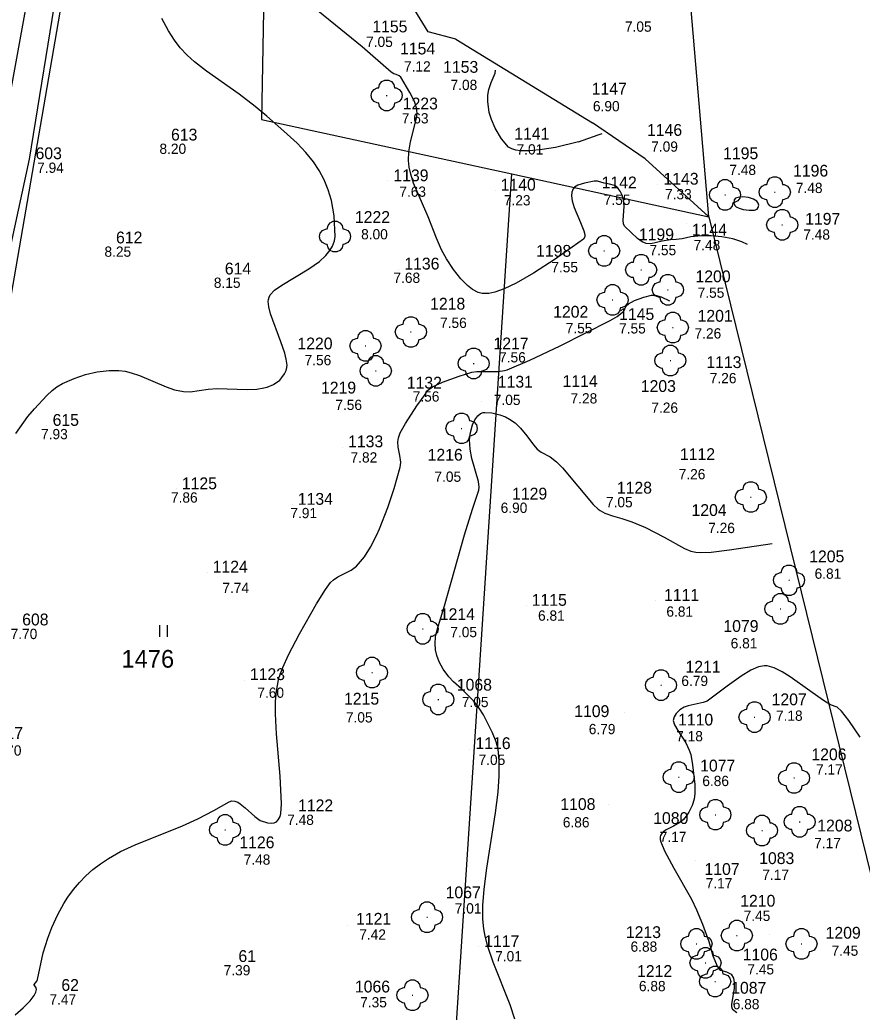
# Model space of a CAD drawing. Extents: x -792549 to -792339, y -1111914 to -1111617.
# Drawn here: x -792466.04 to -792438.93, y -1111801.86 to -1111769.94 of the extents above; entities that cross this region are included whole.
import ezdxf

# ---------------------------------------------------------------- set-up
doc = ezdxf.new("R2010")
doc.units = 0
for name, color, linetype in [('Vrstva 1', 7, 'Continuous'), ('Vrstva 10', 7, 'Continuous'), ('Vrstva 32', 7, 'Continuous'), ('Vrstva 33', 7, 'Continuous'), ('Vrstva 41', 7, 'Continuous'), ('Vrstva 42', 7, 'Continuous'), ('Vrstva 44', 7, 'Continuous'), ('Vrstva 46', 7, 'Continuous'), ('Vrstva 48', 7, 'Continuous'), ('Vrstva 49', 7, 'Continuous'), ('Vrstva 50', 7, 'Continuous')]:
    doc.layers.add(name, color=color, linetype=linetype)

# ---------------------------------------------------------------- blocks, each defined once
blk = doc.blocks.new('3$0600')
at = {"layer": 'Vrstva 1'}
for p, q in [((-5, 15), (-5, 0)), ((5, 0), (5, 15))]:
    blk.add_line(p, q, dxfattribs=at)
blk = doc.blocks.new('SC6231')
at = {"layer": 'Vrstva 1'}
blk.add_line((0, 0), (0, 0), dxfattribs=at)
blk = doc.blocks.new('3$1300')
at = {"layer": 'Vrstva 1'}
for points in [[(20, 0), (19, -4.3), (16.2, -7.8), (12.2, -9.7), (10, -10), (9, -14.3), (6.2, -17.8), (2.2, -19.7), (-2.3, -19.7), (-6.3, -17.8), (-9.1, -14.3), (-10.1, -10), (-12.3, -9.7), (-16.3, -7.8), (-19.1, -4.3), (-20.1, 0), (-19.1, 4.3), (-16.3, 7.8), (-12.3, 9.7), (-10.1, 10), (-9.1, 14.3), (-6.3, 17.8), (-2.3, 19.7), (2.2, 19.7), (6.2, 17.8), (9, 14.3), (10, 10), (12.2, 9.7), (16.2, 7.8), (19, 4.3), (20, 0)], [(-0.5, 0), (0, 0), (0.5, 0)]]:
    blk.add_lwpolyline(points, dxfattribs=at)

msp = doc.modelspace()

# ---------------------------------------------------------------- linework, layer by layer
at = {"layer": 'Vrstva 10'}
for p, q in [((-792452.01, -1111770.56), (-792447.61, -1111773.25)), ((-792445.91, -1111774.41), (-792447.61, -1111773.25)), ((-792445.91, -1111774.41), (-792443.86, -1111776.27))]:
    msp.add_line(p, q, dxfattribs=at)
msp.add_lwpolyline([(-792452.01, -1111770.56), (-792452.9, -1111770.32), (-792453.32, -1111769.63), (-792453.87, -1111768.96), (-792455.06, -1111766.69), (-792455.4, -1111763.77), (-792455.2, -1111759.42), (-792454.58, -1111756.26)], dxfattribs=at)
at = {"layer": 'Vrstva 32'}
for points in [[(-792466.167, -1111783.244), (-792465.781, -1111782.703), (-792465.562, -1111782.449), (-792465.168, -1111782.023), (-792464.995, -1111781.864), (-792464.848, -1111781.748), (-792464.659, -1111781.638), (-792464.293, -1111781.476), (-792463.922, -1111781.352), (-792463.543, -1111781.263), (-792463.161, -1111781.214), (-792462.851, -1111781.219), (-792462.647, -1111781.245), (-792462.451, -1111781.289), (-792462.187, -1111781.376), (-792461.328, -1111781.747), (-792461.056, -1111781.842), (-792460.774, -1111781.9), (-792460.559, -1111781.91), (-792459.98, -1111781.817), (-792459.69, -1111781.8), (-792458.721, -1111781.83), (-792458.408, -1111781.817), (-792458.185, -1111781.782), (-792458.078, -1111781.756), (-792457.872, -1111781.672), (-792457.669, -1111781.527), (-792457.6, -1111781.447), (-792457.516, -1111781.323), (-792457.464, -1111781.218), (-792457.439, -1111781.125), (-792457.434, -1111781.046), (-792457.463, -1111780.854), (-792457.512, -1111780.662), (-792457.633, -1111780.297), (-792457.965, -1111779.394), (-792458.024, -1111779.173), (-792458.041, -1111779.001), (-792458.035, -1111778.931), (-792458.015, -1111778.86), (-792457.979, -1111778.79), (-792457.84, -1111778.639), (-792457.604, -1111778.469), (-792456.737, -1111777.953), (-792456.397, -1111777.707), (-792456.19, -1111777.515), (-792456.06, -1111777.356), (-792455.975, -1111777.219), (-792455.91, -1111777.048), (-792455.89, -1111776.91), (-792455.924, -1111776.238), (-792456.009, -1111775.751), (-792456.111, -1111775.406), (-792456.244, -1111775.083), (-792456.401, -1111774.786), (-792456.583, -1111774.51), (-792456.832, -1111774.202), (-792457.113, -1111773.908), (-792457.536, -1111773.521), (-792458.086, -1111773.039), (-792458.459, -1111772.726), (-792458.98, -1111772.333), (-792460.029, -1111771.591), (-792460.42, -1111771.286), (-792460.656, -1111771.074), (-792460.875, -1111770.843), (-792461.064, -1111770.592), (-792461.248, -1111770.296), (-792461.463, -1111769.894)], [(-792448.055, -1111773.866), (-792448.799, -1111774.042), (-792449.222, -1111774.114), (-792449.619, -1111774.151), (-792449.908, -1111774.147), (-792450.071, -1111774.127), (-792450.201, -1111774.089), (-792450.306, -1111774.029), (-792450.54, -1111773.763), (-792450.737, -1111773.424), (-792450.857, -1111773.14), (-792450.928, -1111772.923), (-792450.98, -1111772.562), (-792450.973, -1111772.356), (-792450.943, -1111772.18), (-792450.869, -1111771.954), (-792450.743, -1111771.648), (-792450.726, -1111771.554)], [(-792448.055, -1111773.866), (-792447.425, -1111773.636), (-792447.299, -1111773.59)], [(-792451.276, -1111784.792), (-792451.491, -1111784.047), (-792451.549, -1111783.745), (-792451.565, -1111783.45), (-792451.537, -1111783.214), (-792451.467, -1111782.966), (-792451.392, -1111782.805), (-792451.302, -1111782.682), (-792451.21, -1111782.604), (-792451.128, -1111782.571), (-792451.068, -1111782.566), (-792450.846, -1111782.584), (-792450.594, -1111782.641), (-792450.409, -1111782.712), (-792450.275, -1111782.78), (-792450.097, -1111782.906), (-792449.92, -1111783.076), (-792449.724, -1111783.321), (-792449.509, -1111783.613), (-792449.386, -1111783.748), (-792449.257, -1111783.848), (-792448.965, -1111784.002), (-792448.77, -1111784.155), (-792448.572, -1111784.354), (-792447.587, -1111785.527), (-792447.428, -1111785.679), (-792447.358, -1111785.727), (-792447.214, -1111785.805), (-792446.967, -1111785.897), (-792446.664, -1111785.98), (-792446.345, -1111786.085), (-792445.905, -1111786.273), (-792445.297, -1111786.578), (-792444.641, -1111786.949), (-792444.445, -1111787.031), (-792444.28, -1111787.069), (-792444.125, -1111787.08), (-792443.793, -1111787.064), (-792443.197, -1111786.988), (-792441.824, -1111786.785)], [(-792450.106, -1111802.093), (-792450.258, -1111801.629), (-792450.801, -1111800.255), (-792450.979, -1111799.751), (-792451.064, -1111799.424), (-792451.107, -1111799.184), (-792451.135, -1111798.867), (-792451.136, -1111798.434), (-792451.098, -1111797.907), (-792451.01, -1111797.231), (-792450.724, -1111795.453), (-792450.642, -1111794.787), (-792450.606, -1111794.256), (-792450.61, -1111793.762), (-792450.647, -1111793.398), (-792450.707, -1111793.162), (-792450.82, -1111792.882), (-792451.117, -1111792.294), (-792451.25, -1111792.078), (-792451.441, -1111791.845), (-792451.814, -1111791.47), (-792452.077, -1111791.235), (-792452.23, -1111791.074), (-792452.411, -1111790.825), (-792452.539, -1111790.593), (-792452.619, -1111790.387), (-792452.659, -1111790.206), (-792452.674, -1111790.008), (-792452.658, -1111789.789), (-792452.611, -1111789.567), (-792452.365, -1111788.793), (-792451.721, -1111786.504), (-792451.467, -1111785.685), (-792451.263, -1111785.065), (-792451.252, -1111784.968), (-792451.276, -1111784.792)], [(-792438.995, -1111793.017), (-792439.359, -1111792.485), (-792439.599, -1111792.182), (-792439.735, -1111792.054), (-792439.944, -1111791.972), (-792440.174, -1111791.841), (-792440.618, -1111791.531), (-792441.241, -1111791.08), (-792441.501, -1111790.917), (-792441.756, -1111790.79), (-792441.987, -1111790.72), (-792442.073, -1111790.718), (-792442.267, -1111790.755), (-792442.509, -1111790.866), (-792442.825, -1111791.056), (-792443.277, -1111791.379), (-792443.918, -1111791.856), (-792444.042, -1111791.901), (-792444.531, -1111792.005), (-792444.661, -1111792.055), (-792444.793, -1111792.137), (-792444.915, -1111792.254), (-792444.984, -1111792.363), (-792445.007, -1111792.475), (-792444.969, -1111792.616), (-792444.864, -1111792.8), (-792444.607, -1111793.195), (-792444.491, -1111793.433), (-792444.446, -1111793.574), (-792444.386, -1111793.91), (-792444.319, -1111794.542), (-792444.311, -1111794.833), (-792444.337, -1111795.009), (-792444.403, -1111795.211), (-792444.509, -1111795.431), (-792444.589, -1111795.557), (-792444.682, -1111795.666), (-792444.797, -1111795.763), (-792444.998, -1111795.879), (-792445.255, -1111796.007), (-792445.363, -1111796.09), (-792445.421, -1111796.179), (-792445.429, -1111796.221), (-792445.425, -1111796.311), (-792445.408, -1111796.389), (-792445.291, -1111796.67), (-792444.989, -1111797.226), (-792444.423, -1111798.233), (-792444.255, -1111798.567), (-792444.07, -1111799.03), (-792443.864, -1111799.594), (-792443.73, -1111800.055), (-792443.583, -1111800.403), (-792443.515, -1111800.496), (-792443.485, -1111800.516), (-792443.294, -1111800.566), (-792443.142, -1111800.641), (-792443.074, -1111800.769), (-792443.048, -1111800.906), (-792443.053, -1111801.094), (-792443.133, -1111801.615), (-792443.133, -1111801.677), (-792443.115, -1111801.755), (-792443.102, -1111801.772), (-792442.966, -1111801.872)]]:
    msp.add_lwpolyline(points, dxfattribs=at)
at = {"layer": 'Vrstva 33'}
for points in [[(-792442.62, -1111777.166), (-792442.796, -1111777.078), (-792443.086, -1111776.985), (-792443.447, -1111776.914), (-792443.788, -1111776.882), (-792444.101, -1111776.884), (-792444.447, -1111776.92), (-792444.725, -1111776.98), (-792444.912, -1111777.005), (-792445.092, -1111777.015), (-792445.36, -1111777.06), (-792445.734, -1111777.14), (-792445.884, -1111777.135), (-792446.007, -1111777.083), (-792446.162, -1111776.973), (-792446.567, -1111776.581), (-792446.607, -1111776.513), (-792446.617, -1111776.391), (-792446.592, -1111775.936), (-792446.607, -1111775.728), (-792446.649, -1111775.575), (-792446.713, -1111775.449), (-792446.815, -1111775.325), (-792446.896, -1111775.271), (-792447.061, -1111775.222), (-792447.231, -1111775.189), (-792447.45, -1111775.128), (-792447.553, -1111775.13), (-792447.868, -1111775.192), (-792448.08, -1111775.26), (-792448.185, -1111775.326), (-792448.229, -1111775.378), (-792448.268, -1111775.483), (-792448.282, -1111775.6), (-792448.264, -1111775.76), (-792448.201, -1111775.974), (-792447.988, -1111776.462), (-792447.883, -1111776.722), (-792447.856, -1111776.847), (-792447.859, -1111776.922), (-792447.897, -1111776.99), (-792448.804, -1111777.633), (-792449.51, -1111778.086), (-792450.068, -1111778.405), (-792450.452, -1111778.592), (-792450.753, -1111778.702), (-792450.944, -1111778.743), (-792451.162, -1111778.746), (-792451.288, -1111778.711), (-792451.465, -1111778.614), (-792451.629, -1111778.483), (-792451.84, -1111778.271), (-792452.082, -1111777.97), (-792452.309, -1111777.626), (-792452.467, -1111777.335), (-792452.631, -1111776.957), (-792452.898, -1111776.274), (-792453.372, -1111775.194), (-792453.458, -1111774.905), (-792453.512, -1111774.68), (-792453.532, -1111774.46), (-792453.521, -1111774.185), (-792453.468, -1111773.862), (-792453.27, -1111773.105), (-792453.251, -1111772.944), (-792453.266, -1111772.769), (-792453.335, -1111772.563), (-792453.483, -1111772.28), (-792453.777, -1111771.782), (-792453.828, -1111771.734), (-792453.923, -1111771.696), (-792454.004, -1111771.676), (-792454.087, -1111771.618), (-792455.021, -1111770.805), (-792457.138, -1111769.074)], [(-792443.048, -1111775.723), (-792443.061, -1111775.833), (-792443.028, -1111775.906), (-792442.98, -1111775.951), (-792442.886, -1111775.998), (-792442.756, -1111776.034), (-792442.567, -1111776.058), (-792442.396, -1111776.056), (-792442.313, -1111776.026), (-792442.271, -1111775.979), (-792442.257, -1111775.903), (-792442.273, -1111775.839), (-792442.323, -1111775.768), (-792442.424, -1111775.702), (-792442.584, -1111775.648), (-792442.771, -1111775.63), (-792442.922, -1111775.649), (-792443, -1111775.677), (-792443.048, -1111775.723)], [(-792458.782, -1111795.293), (-792458.478, -1111795.572), (-792458.304, -1111795.693), (-792458.068, -1111795.774), (-792457.951, -1111795.785), (-792457.856, -1111795.77), (-792457.779, -1111795.736), (-792457.718, -1111795.68), (-792457.66, -1111795.566), (-792457.636, -1111795.47), (-792457.62, -1111795.166), (-792457.659, -1111794.275), (-792457.78, -1111792.909), (-792457.81, -1111792.267), (-792457.805, -1111791.867), (-792457.78, -1111791.539), (-792457.715, -1111791.174), (-792457.692, -1111791.089), (-792457.578, -1111790.779), (-792457.393, -1111790.371), (-792457.037, -1111789.688), (-792456.493, -1111788.731), (-792456.201, -1111788.265), (-792456.036, -1111788.04), (-792455.942, -1111787.949), (-792455.798, -1111787.856), (-792455.369, -1111787.645), (-792455.198, -1111787.515), (-792454.949, -1111787.212), (-792454.755, -1111786.908), (-792454.562, -1111786.527), (-792454.467, -1111786.309), (-792454.198, -1111785.629), (-792453.986, -1111785.013), (-792453.797, -1111784.326), (-792453.785, -1111784.266), (-792453.78, -1111784.166), (-792453.811, -1111783.955), (-792453.862, -1111783.689), (-792453.87, -1111783.516), (-792453.85, -1111783.385), (-792453.792, -1111783.226), (-792453.628, -1111782.927), (-792453.263, -1111782.36), (-792452.995, -1111781.989), (-792452.92, -1111781.86), (-792452.752, -1111781.744), (-792452.435, -1111781.598), (-792451.897, -1111781.403), (-792451.489, -1111781.278), (-792451.33, -1111781.256), (-792450.638, -1111781.248), (-792450.435, -1111781.22), (-792450.355, -1111781.194), (-792449.622, -1111780.884), (-792448.649, -1111780.427), (-792447.041, -1111779.608), (-792446.81, -1111779.478), (-792446.637, -1111779.345), (-792446.599, -1111779.307), (-792446.525, -1111779.137), (-792446.452, -1111779.071), (-792446.26, -1111778.97), (-792445.957, -1111778.856), (-792445.71, -1111778.795), (-792445.589, -1111778.798), (-792445.394, -1111778.849), (-792445.133, -1111778.978)], [(-792466.189, -1111801.949), (-792465.931, -1111801.729), (-792465.701, -1111801.497), (-792465.573, -1111801.331), (-792465.52, -1111801.219), (-792465.496, -1111801.136), (-792465.51, -1111801.083), (-792465.574, -1111800.981), (-792465.573, -1111800.969), (-792465.49, -1111800.87), (-792465.463, -1111800.813), (-792465.287, -1111799.96), (-792465.134, -1111799.479), (-792465.008, -1111799.143), (-792464.814, -1111798.72), (-792464.619, -1111798.367), (-792464.493, -1111798.167), (-792464.312, -1111797.92), (-792464.117, -1111797.69), (-792463.908, -1111797.476), (-792463.684, -1111797.277), (-792463.444, -1111797.092), (-792463.188, -1111796.921), (-792462.793, -1111796.698), (-792462.326, -1111796.477), (-792460.805, -1111795.871), (-792460.303, -1111795.642), (-792459.788, -1111795.376), (-792459.3, -1111795.099), (-792459.212, -1111795.07), (-792459.12, -1111795.075), (-792459.023, -1111795.111), (-792458.944, -1111795.159), (-792458.782, -1111795.293)]]:
    msp.add_lwpolyline(points, dxfattribs=at)
at = {"layer": 'Vrstva 41'}
for points in [[(-792499.397, -1111853.646), (-792494.1, -1111845.56), (-792483.13, -1111826.39), (-792475.49, -1111807.79), (-792471.93, -1111798.6), (-792466.47, -1111779.7), (-792460.34, -1111744.2), (-792459.7, -1111739.09), (-792459.79, -1111725.74), (-792461.41, -1111719.58)], [(-792450.2, -1111774.89), (-792443.86, -1111776.27), (-792444.71, -1111766.33), (-792452, -1111765.8), (-792452.96, -1111743.8), (-792459.7, -1111739.09)], [(-792460.34, -1111744.2), (-792457.78, -1111746.94), (-792458.26, -1111773.14), (-792450.2, -1111774.89)], [(-792471.93, -1111798.6), (-792453.26, -1111821.81), (-792450.2, -1111774.89)], [(-792443.86, -1111776.27), (-792434.42, -1111814.6), (-792402.33, -1111815.45), (-792402.93, -1111822.06), (-792405.11, -1111832), (-792444.2, -1111829.87)]]:
    msp.add_lwpolyline(points, dxfattribs=at)
at = {"layer": 'Vrstva 46'}
for points in [[(-792463.81, -1111758.3), (-792466.51, -1111773.18), (-792468.17, -1111779.96), (-792470.36, -1111787.72), (-792472.8, -1111795.11)], [(-792470.98, -1111792.25), (-792469.24, -1111787.51), (-792467.12, -1111780.83), (-792465.73, -1111774.42), (-792463.86, -1111762.91)]]:
    msp.add_lwpolyline(points, dxfattribs=at)

# ---------------------------------------------------------------- block references
at = {"layer": 'Vrstva 42', "xscale": 0.025, "yscale": 0.025000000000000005, "rotation": 0.3875643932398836}
msp.add_blockref('3$0600', (-792461.412, -1111789.786), dxfattribs=at)
at = {"layer": 'Vrstva 44', "xscale": 0.025, "yscale": 0.025000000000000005}
for p in [(-792454.23, -1111772.37), (-792441.74, -1111775.48), (-792443.34, -1111775.57), (-792441.5, -1111776.53), (-792455.89, -1111776.91), (-792447.23, -1111777.37), (-792446.04, -1111777.98), (-792445.18, -1111778.62), (-792446.96, -1111778.95), (-792445.02, -1111779.84), (-792453.45, -1111779.98), (-792454.91, -1111780.43), (-792445.1, -1111780.9), (-792454.58, -1111781.23), (-792451.43, -1111780.99), (-792451.82, -1111783.08), (-792442.51, -1111785.29), (-792441.28, -1111787.97), (-792441.56, -1111788.89), (-792453.07, -1111789.53), (-792454.7, -1111790.94), (-792445.4, -1111791.34), (-792452.57, -1111791.8), (-792442.39, -1111792.37), (-792444.83, -1111794.3), (-792441.12, -1111794.33), (-792443.65, -1111795.51), (-792440.94, -1111795.74), (-792459.43, -1111796), (-792442.15, -1111796.02), (-792452.93, -1111798.81), (-792442.96, -1111799.4), (-792444.26, -1111799.67), (-792440.88, -1111799.67), (-792443.97, -1111800.28), (-792443.66, -1111800.88), (-792453.4, -1111801.32)]:
    msp.add_blockref('3$1300', p, dxfattribs=at)
at = {"layer": 'Vrstva 48', "xscale": 0.1, "yscale": 0.10000000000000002}
for p in [(-792452.9, -1111770.32), (-792452.01, -1111770.56), (-792454.23, -1111772.37), (-792447.61, -1111773.25), (-792461.37, -1111773.81), (-792450.41, -1111774.05), (-792465.73, -1111774.42), (-792445.91, -1111774.41), (-792454.21, -1111775.12), (-792445.5, -1111775.23), (-792450.74, -1111775.43), (-792447.49, -1111775.35), (-792443.34, -1111775.57), (-792441.74, -1111775.48), (-792444.57, -1111776.49), (-792441.5, -1111776.53), (-792455.89, -1111776.91), (-792463.14, -1111777.12), (-792447.23, -1111777.37), (-792459.62, -1111778.12), (-792453.84, -1111777.96), (-792446.04, -1111777.98), (-792445.88, -1111778.54), (-792445.18, -1111778.62), (-792446.96, -1111778.95), (-792453.45, -1111779.98), (-792445.02, -1111779.84), (-792454.91, -1111780.43), (-792451.43, -1111780.99), (-792445.1, -1111780.9), (-792444.08, -1111780.88), (-792454.58, -1111781.23), (-792453.22, -1111781.78), (-792447.47, -1111781.84), (-792451.17, -1111782.22), (-792465.18, -1111782.99), (-792451.82, -1111783.08), (-792455.65, -1111783.69), (-792444.29, -1111784.23), (-792461, -1111785.03), (-792447, -1111785.18), (-792457.25, -1111785.53), (-792450.39, -1111785.36), (-792442.51, -1111785.29), (-792459.99, -1111787.71), (-792441.28, -1111787.97), (-792445.59, -1111788.62), (-792449.74, -1111788.78), (-792441.56, -1111788.89), (-792453.07, -1111789.53), (-792454.7, -1111790.94), (-792458.81, -1111791.18), (-792445.4, -1111791.34), (-792452.57, -1111791.8), (-792446.58, -1111792.23), (-792442.39, -1111792.37), (-792444, -1111792.65), (-792451.55, -1111793.4), (-792444.83, -1111794.3), (-792441.12, -1111794.33), (-792457.26, -1111795.4), (-792447.09, -1111795.19), (-792443.65, -1111795.51), (-792440.94, -1111795.74), (-792459.43, -1111796), (-792442.15, -1111796.02), (-792444.28, -1111797), (-792452.93, -1111798.81), (-792455.48, -1111799.06), (-792442.96, -1111799.4), (-792441.9, -1111799.35), (-792451.27, -1111799.76), (-792444.26, -1111799.67), (-792440.88, -1111799.67), (-792459.32, -1111800.24), (-792443.97, -1111800.28), (-792464.91, -1111801.18), (-792443.66, -1111800.88), (-792453.4, -1111801.32)]:
    msp.add_blockref('SC6231', p, dxfattribs=at)

# ---------------------------------------------------------------- texts
at = {"layer": 'Vrstva 42'}
msp.add_text('1476', height=0.57, dxfattribs=at).set_placement((-792462.766, -1111790.78))
at = {"layer": 'Vrstva 49'}
for s, p in [('1155', (-792454.693, -1111770.34)), ('1154', (-792453.801, -1111771.05)), ('1153', (-792452.414, -1111771.641)), ('1147', (-792447.633, -1111772.34)), ('1223', (-792453.713, -1111772.82)), ('1141', (-792450.125, -1111773.789)), ('1146', (-792445.853, -1111773.67)), ('613', (-792461.171, -1111773.82)), ('603', (-792465.531, -1111774.42)), ('1195', (-792443.403, -1111774.42)), ('1196', (-792441.153, -1111774.98)), ('1139', (-792454.015, -1111775.13)), ('1142', (-792447.313, -1111775.36)), ('1143', (-792445.323, -1111775.24)), ('1140', (-792450.563, -1111775.43)), ('1222', (-792455.253, -1111776.47)), ('1197', (-792440.763, -1111776.53)), ('1144', (-792444.411, -1111776.88)), ('612', (-792462.941, -1111777.13)), ('1199', (-792446.115, -1111777.03)), ('1198', (-792449.423, -1111777.56)), ('614', (-792459.44, -1111778.13)), ('1136', (-792453.663, -1111777.97)), ('1200', (-792444.293, -1111778.38)), ('1218', (-792452.833, -1111779.26)), ('1202', (-792448.873, -1111779.52)), ('1145', (-792446.75, -1111779.594)), ('1201', (-792444.225, -1111779.65)), ('1220', (-792457.103, -1111780.54)), ('1217', (-792450.793, -1111780.54)), ('1113', (-792443.944, -1111781.141)), ('1131', (-792450.655, -1111781.77)), ('1114', (-792448.571, -1111781.75)), ('1219', (-792456.345, -1111781.96)), ('1132', (-792453.583, -1111781.8)), ('1203', (-792446.053, -1111781.91)), ('615', (-792464.981, -1111783)), ('1133', (-792455.473, -1111783.69)), ('1216', (-792452.913, -1111784.12)), ('1112', (-792444.793, -1111784.1)), ('1125', (-792460.823, -1111785.04)), ('1128', (-792446.823, -1111785.18)), ('1134', (-792457.091, -1111785.54)), ('1129', (-792450.195, -1111785.37)), ('1204', (-792444.421, -1111785.9)), ('1205', (-792440.633, -1111787.39)), ('1124', (-792459.831, -1111787.72)), ('1115', (-792449.563, -1111788.79)), ('1111', (-792445.305, -1111788.63)), ('608', (-792465.961, -1111789.42)), ('1214', (-792452.521, -1111789.25)), ('1079', (-792443.395, -1111789.63)), ('1211', (-792444.615, -1111790.94)), ('1123', (-792458.633, -1111791.18)), ('1068', (-792451.973, -1111791.52)), ('1215', (-792455.603, -1111791.969)), ('1207', (-792441.843, -1111791.99)), ('1109', (-792448.195, -1111792.37)), ('1110', (-792444.853, -1111792.64)), ('517', (-792466.781, -1111793.07)), ('1116', (-792451.373, -1111793.4)), ('1206', (-792440.563, -1111793.76)), ('1077', (-792444.143, -1111794.12)), ('1122', (-792457.083, -1111795.4)), ('1108', (-792448.643, -1111795.36)), ('1080', (-792445.653, -1111795.81)), ('1208', (-792440.373, -1111796.05)), ('1126', (-792458.973, -1111796.59)), ('1083', (-792442.243, -1111797.1)), ('1107', (-792444.003, -1111797.45)), ('1067', (-792452.333, -1111798.2)), ('1210', (-792442.853, -1111798.47)), ('1121', (-792455.215, -1111799.05)), ('1213', (-792446.533, -1111799.48)), ('1209', (-792440.105, -1111799.5)), ('1117', (-792451.093, -1111799.77)), ('61', (-792459.001, -1111800.25)), ('1106', (-792442.773, -1111800.2)), ('1212', (-792446.173, -1111800.73)), ('62', (-792464.7, -1111801.18)), ('1066', (-792455.253, -1111801.23)), ('1087', (-792443.143, -1111801.27))]:
    msp.add_text(s, height=0.38, dxfattribs=at).set_placement(p)
at = {"layer": 'Vrstva 50'}
for s, p in [('7.05', (-792446.563, -1111770.32)), ('7.05', (-792454.893, -1111770.81)), ('7.12', (-792453.673, -1111771.6)), ('7.08', (-792452.175, -1111772.196)), ('6.90', (-792447.593, -1111772.88)), ('7.63', (-792453.743, -1111773.27)), ('8.20', (-792461.543, -1111774.25)), ('7.01', (-792450.05, -1111774.27)), ('7.09', (-792445.717, -1111774.18)), ('7.94', (-792465.479, -1111774.86)), ('7.48', (-792443.203, -1111774.93)), ('7.63', (-792453.823, -1111775.63)), ('7.48', (-792441.063, -1111775.51)), ('7.23', (-792450.461, -1111775.908)), ('7.55', (-792447.245, -1111775.892)), ('7.33', (-792445.273, -1111775.71)), ('8.00', (-792455.053, -1111777)), ('7.48', (-792440.823, -1111777.01)), ('8.25', (-792463.313, -1111777.56)), ('7.55', (-792445.773, -1111777.51)), ('7.48', (-792444.353, -1111777.35)), ('7.55', (-792448.933, -1111778.06)), ('7.68', (-792454.013, -1111778.4)), ('8.15', (-792459.793, -1111778.56)), ('7.55', (-792444.223, -1111778.88)), ('7.56', (-792452.513, -1111779.85)), ('7.55', (-792448.469, -1111780.022)), ('7.55', (-792446.751, -1111780.029)), ('7.26', (-792444.323, -1111780.19)), ('7.56', (-792456.873, -1111781.05)), ('7.56', (-792450.613, -1111780.96)), ('7.26', (-792443.833, -1111781.629)), ('7.56', (-792453.393, -1111782.22)), ('7.05', (-792450.783, -1111782.33)), ('7.28', (-792448.313, -1111782.28)), ('7.56', (-792455.883, -1111782.49)), ('7.26', (-792445.713, -1111782.58)), ('7.93', (-792465.353, -1111783.43)), ('7.82', (-792455.393, -1111784.18)), ('7.05', (-792452.693, -1111784.8)), ('7.26', (-792444.833, -1111784.72)), ('7.86', (-792461.173, -1111785.47)), ('6.90', (-792450.563, -1111785.8)), ('7.05', (-792447.173, -1111785.62)), ('7.91', (-792457.329, -1111785.97)), ('7.26', (-792443.883, -1111786.45)), ('6.81', (-792440.459, -1111787.92)), ('7.74', (-792459.519, -1111788.38)), ('6.81', (-792449.359, -1111789.27)), ('6.81', (-792445.229, -1111789.14)), ('7.70', (-792466.333, -1111789.86)), ('7.05', (-792452.183, -1111789.8)), ('6.81', (-792443.159, -1111790.16)), ('6.79', (-792444.747, -1111791.37)), ('7.60', (-792458.393, -1111791.75)), ('7.05', (-792451.813, -1111792.05)), ('7.05', (-792455.543, -1111792.544)), ('7.18', (-792441.703, -1111792.49)), ('6.79', (-792447.727, -1111792.92)), ('7.18', (-792444.913, -1111793.15)), ('7.70', (-792466.843, -1111793.61)), ('7.05', (-792451.273, -1111793.91)), ('7.17', (-792440.413, -1111794.22)), ('6.86', (-792444.073, -1111794.59)), ('7.48', (-792457.433, -1111795.84)), ('6.86', (-792448.563, -1111795.92)), ('7.17', (-792445.443, -1111796.39)), ('7.17', (-792440.473, -1111796.59)), ('7.48', (-792458.833, -1111797.12)), ('7.17', (-792442.143, -1111797.61)), ('7.17', (-792443.963, -1111797.88)), ('7.01', (-792452.039, -1111798.69)), ('7.45', (-792442.743, -1111798.93)), ('7.42', (-792455.113, -1111799.53)), ('6.88', (-792446.383, -1111799.92)), ('7.01', (-792450.739, -1111800.23)), ('7.45', (-792439.913, -1111800.05)), ('7.39', (-792459.477, -1111800.68)), ('7.45', (-792442.623, -1111800.65)), ('6.88', (-792446.113, -1111801.19)), ('7.47', (-792465.083, -1111801.62)), ('7.35', (-792455.083, -1111801.71)), ('6.88', (-792443.093, -1111801.77))]:
    msp.add_text(s, height=0.33, dxfattribs=at).set_placement(p)

doc.saveas('drawing.dxf')
